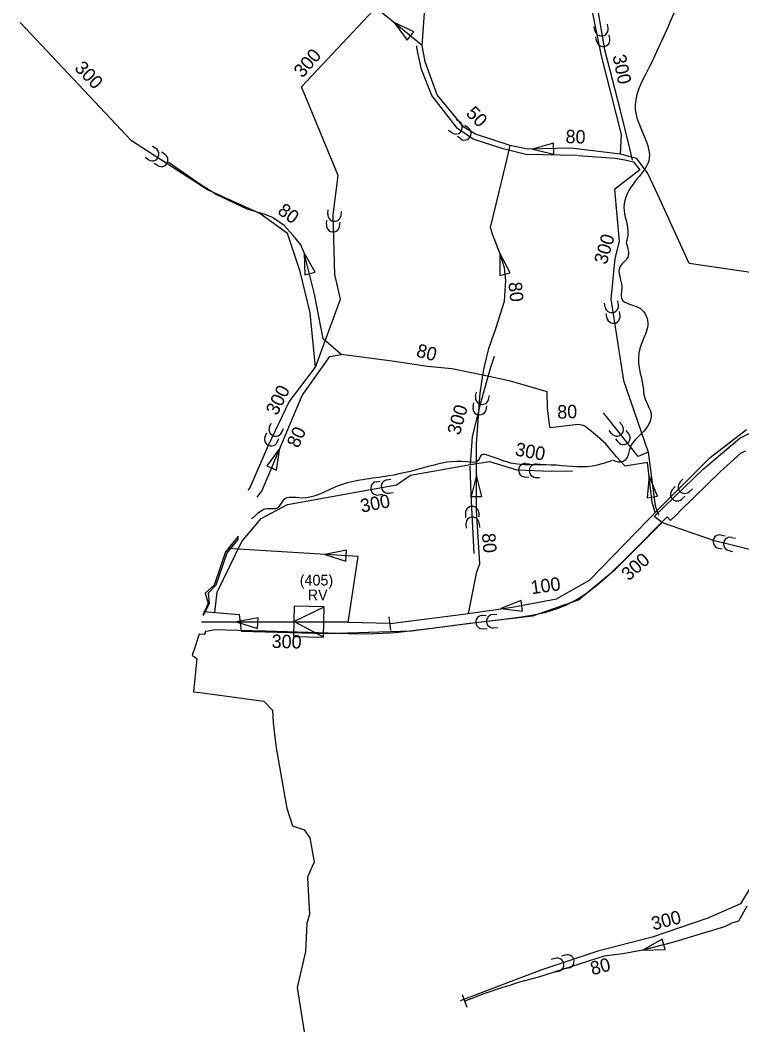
# Model space of a CAD drawing. Extents: x -438814 to -433692, y -1130252 to -1121149.
# Drawn here: x -438788 to -438249, y -1124695 to -1123942 of the extents above; entities that cross this region are included whole.
import ezdxf

# ---------------------------------------------------------------- set-up
doc = ezdxf.new("R2010")
doc.units = 0
for name, color, linetype in [('Vrstva 10', 7, 'Continuous'), ('Vrstva 11', 7, 'Continuous'), ('Vrstva 12', 7, 'Continuous'), ('Vrstva 13', 7, 'Continuous'), ('Vrstva 14', 7, 'Continuous'), ('Vrstva 19', 7, 'Continuous'), ('Vrstva 34', 7, 'Continuous'), ('Vrstva 36', 7, 'Continuous'), ('Vrstva 38', 7, 'Continuous'), ('Vrstva 39', 7, 'Continuous'), ('Vrstva 46', 7, 'Continuous'), ('Vrstva 48', 7, 'Continuous'), ('Vrstva 49', 7, 'Continuous'), ('WT - vodni a vodnich toku', 7, 'Continuous')]:
    doc.layers.add(name, color=color, linetype=linetype)

# ---------------------------------------------------------------- blocks, each defined once
blk = doc.blocks.new('REDUK2')
at = {"layer": 'Vrstva 11'}
for p, q in [((11.906, 10.975), (-10.548, 10.975)), ((-10.548, 10.975), (-10.548, -11.657)), ((-10.548, 10.975), (11.906, -0.341)), ((11.906, -11.657), (11.906, 10.975)), ((11.906, -0.341), (-10.548, -11.657)), ((-10.548, -11.657), (11.906, -11.657))]:
    blk.add_line(p, q, dxfattribs=at)

msp = doc.modelspace()

# ---------------------------------------------------------------- linework, layer by layer
at = {"layer": 'Vrstva 11'}
for points in [[(-438442.88, -1124207.02), (-438441.6, -1124200.42), (-438438.29, -1124186.93), (-438433.03, -1124171.38), (-438426.62, -1124151.63), (-438425.76, -1124136.25), (-438426.82, -1124126.85), (-438430.11, -1124115.96), (-438435.77, -1124101.69), (-438437.1, -1124096.6), (-438432.95, -1124079.29), (-438425.3, -1124047.44), (-438422.48, -1124035.55)], [(-438314.06, -1124309.51), (-438316.51, -1124302.05), (-438319.82, -1124272.26), (-438336.48, -1124274.95), (-438342.98, -1124267.91), (-438351.11, -1124258.21), (-438359.34, -1124250.97), (-438366.81, -1124245.05), (-438368.77, -1124244.22), (-438371.81, -1124243.9), (-438392.24, -1124246.22), (-438392.92, -1124245.73), (-438394.67, -1124231.5), (-438394.89, -1124219.29), (-438422.3, -1124211.37), (-438442.88, -1124207.02), (-438466, -1124202.27), (-438484.14, -1124200.36), (-438510.72, -1124196.48), (-438548.74, -1124191.47), (-438562.22, -1124179.81), (-438568.66, -1124146.38), (-438576.25, -1124115.64), (-438578.87, -1124109.52), (-438584.21, -1124102.8), (-438591.16, -1124095.15), (-438599.97, -1124089.17), (-438605.49, -1124087.04), (-438618.88, -1124082.96), (-438641.95, -1124072.08), (-438654.16, -1124064.24), (-438677.87, -1124047.92)], [(-438512.15, -1124392.34), (-438453.67, -1124384.87), (-438420.93, -1124380.11), (-438387.77, -1124374.02), (-438363.32, -1124359.98), (-438310.95, -1124306.32), (-438304.05, -1124299.37), (-438273.08, -1124268.41), (-438245.92, -1124247.58)], [(-438245.72, -1124603.41), (-438251.96, -1124614.54), (-438256.93, -1124616.08), (-438262.32, -1124618.96), (-438301.2, -1124630.58), (-438323.29, -1124636.23), (-438338.38, -1124638.97), (-438352.36, -1124640.67), (-438401.26, -1124656.44), (-438416.53, -1124660.43), (-438423.56, -1124663.01), (-438428.3, -1124664.11), (-438442.18, -1124668.96), (-438456.25, -1124674.44)]]:
    msp.add_lwpolyline(points, dxfattribs=at)
at = {"layer": 'Vrstva 12'}
for p, q in [((-438511.49, -1124397.3), (-438512.81, -1124387.39)), ((-438454.54, -1124679.13), (-438457.96, -1124669.74))]:
    msp.add_line(p, q, dxfattribs=at)
for points in [[(-438575.84, -1124132.13), (-438568.13, -1124130), (-438576.25, -1124115.64)], [(-438430.27, -1124132.45), (-438422.49, -1124130.59), (-438430.11, -1124115.96)], [(-438320.26, -1124298.58), (-438312.34, -1124297.4), (-438318.65, -1124282.16)], [(-438413.15, -1124383.11), (-438414.21, -1124375.18), (-438429.54, -1124381.27)], [(-438306.8, -1124635.89), (-438308.9, -1124628.18), (-438323.29, -1124636.23)]]:
    msp.add_lwpolyline(points, close=True, dxfattribs=at)
at = {"layer": 'Vrstva 13'}
for p, q in [((-438488.31, -1123960.72), (-438538.54, -1123919.74)), ((-438543.49, -1124391.29), (-438653.03, -1124391.29))]:
    msp.add_line(p, q, dxfattribs=at)
for points in [[(-438339.96, -1124041.86), (-438339.19, -1124027.17), (-438354.13, -1123968.53), (-438362.05, -1123930.71), (-438383.31, -1123905.62), (-438391.01, -1123883.43), (-438409.98, -1123853.88), (-438454.8, -1123791.15), (-438466.52, -1123791.91)], [(-438087.24, -1124107.32), (-438135.67, -1124122.18), (-438154.23, -1124128.52), (-438172.8, -1124139.61), (-438230.97, -1124132.14), (-438288.66, -1124123.51), (-438311.91, -1124072.81), (-438319.59, -1124056.35), (-438327.96, -1124045.25), (-438339.96, -1124041.86), (-438377.03, -1124037.56), (-438409.62, -1124038.24), (-438422.48, -1124035.55), (-438448.29, -1124026.95), (-438457.11, -1124021.74), (-438470.02, -1124006.12), (-438477.01, -1123997.55), (-438486.06, -1123973.09), (-438488.31, -1123960.72), (-438482.88, -1123887.58), (-438483.1, -1123883.34)], [(-438611.36, -1124298.04), (-438607.93, -1124293.61), (-438577.83, -1124222.09), (-438557.1, -1124192.91), (-438548.74, -1124191.47)], [(-438453.67, -1124384.87), (-438447.34, -1124353.84), (-438445.07, -1124347.73), (-438447.56, -1124307.87), (-438447.56, -1124262.81), (-438447.56, -1124258.11), (-438444.9, -1124220.51), (-438442.88, -1124207.02)], [(-438512.15, -1124392.34), (-438543.49, -1124391.63), (-438536.02, -1124342.27), (-438633.41, -1124336.42)]]:
    msp.add_lwpolyline(points, dxfattribs=at)
at = {"layer": 'Vrstva 14'}
for points in [[(-438499.36, -1123956.87), (-438494.3, -1123950.67), (-438509.23, -1123943.65)], [(-438389.82, -1124041.83), (-438389.99, -1124033.83), (-438405.9, -1124038.16)], [(-438604.31, -1124274.69), (-438596.94, -1124277.79), (-438594.42, -1124261.49)], [(-438451.56, -1124297.66), (-438443.56, -1124297.66), (-438447.56, -1124281.66)], [(-438545.12, -1124345.73), (-438544.64, -1124337.74), (-438560.85, -1124340.78)], [(-438611.2, -1124396.16), (-438610.72, -1124388.18), (-438626.93, -1124391.21)]]:
    msp.add_lwpolyline(points, close=True, dxfattribs=at)
at = {"layer": 'Vrstva 19'}
msp.add_line((-438640.64, -1124071.78), (-438640.64, -1124071.78), dxfattribs=at)
at = {"layer": 'Vrstva 34'}
for points in [[(-438618.18, -1124292.86), (-438616.82, -1124291.28), (-438603.03, -1124259.33), (-438587.5, -1124226.84), (-438567.82, -1124200.86), (-438571.9, -1124160.37), (-438579.29, -1124129.63), (-438588.73, -1124101.17), (-438609.56, -1124086.22), (-438648.41, -1124068.62), (-438705.23, -1124031.94), (-438788.44, -1123943.51)], [(-438308.92, -1124317.08), (-438270.78, -1124330.05), (-438232.63, -1124339.64), (-438193.93, -1124319.41), (-438110.46, -1124306.7), (-438076.83, -1124294.13), (-438044.07, -1124289.63), (-437999.41, -1124284.16), (-437947.43, -1124273.24), (-437905, -1124250.33), (-437868.85, -1124217.12), (-437841.76, -1124189.51), (-437857.04, -1124146.16), (-437823.32, -1124112.77), (-437798.27, -1124098.47), (-437778.05, -1124070.78), (-437758.37, -1124050.48), (-437737.69, -1124057.16), (-437694.33, -1124068.4)], [(-438651.16, -1124383.4), (-438624.86, -1124385.67), (-438623.42, -1124398.12), (-438559.85, -1124399.77), (-438496.06, -1124397.82), (-438448.11, -1124391.65), (-438405.45, -1124386.56), (-438371.48, -1124374.64), (-438343.9, -1124351.74), (-438308.92, -1124317.08), (-438314.79, -1124312.41), (-438278.32, -1124277.04), (-438250.99, -1124254.05), (-438206.56, -1124231.61)]]:
    msp.add_lwpolyline(points, dxfattribs=at)
at = {"layer": 'Vrstva 36'}
for points in [[(-438331.07, -1124046.44), (-438333.12, -1124037.74), (-438339.96, -1124009.42), (-438351.73, -1123963.91), (-438357.38, -1123930.49), (-438380.02, -1123902.18), (-438387.48, -1123880.05), (-438405.81, -1123851.29), (-438437.69, -1123807.22), (-438456.25, -1123781.63), (-438506.44, -1123713.82), (-438523.22, -1123647.28), (-438584.56, -1123598.88)], [(-438567.82, -1124200.86), (-438549.24, -1124150.11), (-438553.35, -1124131.76), (-438554.62, -1124087.16), (-438550.82, -1124057.86), (-438578.33, -1123991.75), (-438524.57, -1123934.38), (-438630.16, -1123854.33)], [(-438372.19, -1124043.02), (-438410.87, -1124042.12), (-438427.57, -1124038.05), (-438450.2, -1124030.81), (-438461.74, -1124022.88), (-438480.96, -1123998.07), (-438488.66, -1123978.6), (-438492.28, -1123962.52), (-438492.16, -1123961.14)], [(-438371.71, -1124043.03), (-438344.03, -1124044.86), (-438336.76, -1124046.12), (-438330.43, -1124047.71), (-438325.53, -1124053.6), (-438344.66, -1124068.31), (-438341.04, -1124107.22), (-438344.21, -1124119.87), (-438347.37, -1124150.24), (-438337.88, -1124210.97), (-438319.33, -1124264.41), (-438314.08, -1124304.57), (-438311.64, -1124311.6)], [(-438452.19, -1124273.53), (-438450.66, -1124252.99), (-438444.09, -1124226.49), (-438436.85, -1124200.91), (-438434.16, -1124192.76)], [(-438319.33, -1124264.41), (-438326.93, -1124267.68), (-438340.97, -1124249.8), (-438352.74, -1124235.13)], [(-438642.93, -1124384.11), (-438641.36, -1124369.01), (-438622.81, -1124331.25), (-438608.55, -1124314.04), (-438588.86, -1124303.62), (-438507.38, -1124288.9), (-438496.96, -1124281.66), (-438452.19, -1124273.53), (-438437.93, -1124271.49), (-438417.56, -1124277.6), (-438391.84, -1124278.75), (-438376, -1124278.38)], [(-438449.37, -1124340.04), (-438451.64, -1124296.11), (-438452.35, -1124274.97)], [(-438072.31, -1124326.82), (-438070.72, -1124338.14), (-438084.53, -1124374.6), (-438114.66, -1124405.79), (-438142.73, -1124423), (-438145.44, -1124435.91), (-438147.89, -1124449.85), (-438144.26, -1124487.89), (-438198.59, -1124497.85), (-438204.18, -1124509.07), (-438223.42, -1124565.68), (-438241.08, -1124586.06), (-438250.36, -1124601.69), (-438274.72, -1124612.47), (-438316.37, -1124626.51), (-438356.89, -1124637.15), (-438399.67, -1124651.19), (-438459.74, -1124674)]]:
    msp.add_lwpolyline(points, dxfattribs=at)
at = {"layer": 'Vrstva 38'}
for p, q in [((-438687.06, -1124037.71), (-438689.58, -1124036.09)), ((-438680.34, -1124042.05), (-438682.86, -1124040.43)), ((-438692.48, -1124046.11), (-438695, -1124044.49)), ((-438685.76, -1124050.45), (-438688.28, -1124048.83)), ((-438602.17, -1124245.43), (-438600.92, -1124242.7)), ((-438593.08, -1124249.58), (-438591.83, -1124246.86)), ((-438605.5, -1124252.7), (-438604.25, -1124249.97)), ((-438596.4, -1124256.86), (-438595.16, -1124254.13)), ((-438295.54, -1124286.7), (-438293.4, -1124284.6)), ((-438301.25, -1124292.3), (-438299.11, -1124290.2)), ((-438288.54, -1124293.84), (-438286.4, -1124291.74)), ((-438294.25, -1124299.44), (-438292.11, -1124297.34)), ((-438264.78, -1124326.3), (-438261.86, -1124326.97)), ((-438256.99, -1124328.09), (-438254.06, -1124328.76)), ((-438267.02, -1124336.04), (-438264.1, -1124336.72)), ((-438259.23, -1124337.83), (-438256.3, -1124338.51)), ((-438443.49, -1124386.3), (-438440.5, -1124386.07)), ((-438435.51, -1124385.7), (-438432.52, -1124385.48)), ((-438442.75, -1124396.27), (-438439.76, -1124396.05)), ((-438434.77, -1124395.68), (-438431.78, -1124395.46))]:
    msp.add_line(p, q, dxfattribs=at)
for centre, start, end in [((-438689.77, -1124041.91), 237.15049, 57.15156), ((-438683.05, -1124046.25), 237.15049, 57.15156), ((-438597.62, -1124247.5), 155.42113, 335.4222), ((-438600.95, -1124254.78), 155.42113, 335.4222), ((-438297.75, -1124295.87), 134.45249, 314.45356), ((-438292.04, -1124290.27), 134.45249, 314.45356), ((-438265.9, -1124331.17), 77.05789, 257.05896), ((-438258.11, -1124332.96), 77.05789, 257.05896), ((-438443.12, -1124391.28), 94.24012, 274.24119), ((-438435.14, -1124390.69), 94.24012, 274.24119)]:
    msp.add_arc(centre, 5, start, end, dxfattribs=at)
at = {"layer": 'Vrstva 39'}
for p, q in [((-438349.38, -1123947.84), (-438349.88, -1123944.88)), ((-438359.24, -1123949.51), (-438359.74, -1123946.55)), ((-438348.04, -1123955.73), (-438348.54, -1123952.77)), ((-438357.9, -1123957.4), (-438358.41, -1123954.44)), ((-438460.35, -1124017.77), (-438462.83, -1124016.07)), ((-438453.76, -1124022.3), (-438456.23, -1124020.6)), ((-438466.01, -1124026.02), (-438468.49, -1124024.32)), ((-438459.42, -1124030.54), (-438461.89, -1124028.85)), ((-438558.71, -1124086.37), (-438558.33, -1124083.39)), ((-438548.8, -1124087.65), (-438548.41, -1124084.68)), ((-438559.74, -1124094.3), (-438559.35, -1124091.33)), ((-438549.82, -1124095.58), (-438549.44, -1124092.61)), ((-438351.52, -1124156.06), (-438351.98, -1124153.09)), ((-438341.64, -1124154.52), (-438342.1, -1124151.55)), ((-438350.29, -1124163.96), (-438350.75, -1124161)), ((-438340.41, -1124162.42), (-438340.87, -1124159.46)), ((-438448.29, -1124222.65), (-438447.57, -1124219.74)), ((-438438.59, -1124225.05), (-438437.86, -1124222.14)), ((-438450.22, -1124230.42), (-438449.5, -1124227.5)), ((-438440.51, -1124232.82), (-438439.79, -1124229.91)), ((-438338.88, -1124244.37), (-438340.73, -1124242.01)), ((-438346.74, -1124250.55), (-438348.59, -1124248.19)), ((-438341.8, -1124256.84), (-438343.65, -1124254.48)), ((-438333.93, -1124250.66), (-438335.79, -1124248.3)), ((-438411, -1124272.89), (-438408, -1124273.03)), ((-438403.01, -1124273.25), (-438400.01, -1124273.38)), ((-438514.63, -1124285.13), (-438511.68, -1124284.6)), ((-438411.44, -1124282.88), (-438408.44, -1124283.02)), ((-438403.45, -1124283.24), (-438400.45, -1124283.37)), ((-438522.5, -1124286.55), (-438519.55, -1124286.02)), ((-438520.72, -1124296.39), (-438517.77, -1124295.86)), ((-438512.85, -1124294.97), (-438509.9, -1124294.44)), ((-438455.92, -1124310.14), (-438455.77, -1124313.14)), ((-438445.93, -1124309.63), (-438445.78, -1124312.63)), ((-438455.51, -1124318.13), (-438455.35, -1124321.13)), ((-438445.52, -1124317.62), (-438445.37, -1124320.61)), ((-438388.89, -1124642.39), (-438391.73, -1124643.32)), ((-438381.28, -1124639.9), (-438384.13, -1124640.83)), ((-438385.77, -1124651.89), (-438388.62, -1124652.83)), ((-438378.17, -1124649.4), (-438381.02, -1124650.33))]:
    msp.add_line(p, q, dxfattribs=at)
for centre, start, end in [((-438354.31, -1123948.67), 189.5971, 9.59817), ((-438352.97, -1123956.56), 189.5971, 9.59817), ((-438463.18, -1124021.89), 235.53025, 55.53133), ((-438456.59, -1124026.42), 235.53025, 55.53133), ((-438553.75, -1124087.01), 172.62343, 352.6245), ((-438554.78, -1124094.94), 172.62343, 352.6245), ((-438346.58, -1124155.29), 188.87741, 8.87848), ((-438345.35, -1124163.19), 188.87741, 8.87848), ((-438443.44, -1124223.85), 166.08442, 346.08549), ((-438445.36, -1124231.62), 166.08442, 346.08549), ((-438342.81, -1124247.46), 218.14774, 38.14881), ((-438337.87, -1124253.75), 218.14774, 38.14881), ((-438411.22, -1124277.89), 87.4505, 267.45157), ((-438403.23, -1124278.24), 87.4505, 267.45157), ((-438521.61, -1124291.47), 100.2385, 280.23957), ((-438513.74, -1124290.05), 100.2385, 280.23957), ((-438450.93, -1124309.89), 2.94878, 182.94985), ((-438450.52, -1124317.88), 2.94878, 182.94985), ((-438387.33, -1124647.14), 288.16815, 108.16922), ((-438379.72, -1124644.65), 288.16815, 108.16922)]:
    msp.add_arc(centre, 5, start, end, dxfattribs=at)
at = {"layer": 'Vrstva 46'}
for p, q in [((-438655.04, -1124401.08), (-438658.72, -1124412.5)), ((-438658.72, -1124412.5), (-438659.38, -1124414.56)), ((-438659.38, -1124414.56), (-438659.93, -1124416.28)), ((-438659.93, -1124416.28), (-438659.46, -1124416.56)), ((-438659.46, -1124416.56), (-438656.47, -1124418.39)), ((-438656.47, -1124418.39), (-438658.78, -1124440.93)), ((-438658.78, -1124440.93), (-438659.03, -1124443.37)), ((-438659.03, -1124443.37), (-438652.37, -1124444.25)), ((-438652.37, -1124444.25), (-438606.34, -1124450.3)), ((-438606.34, -1124450.3), (-438599.86, -1124457.06)), ((-438599.86, -1124457.06), (-438599.4, -1124466.49)), ((-438599.4, -1124466.49), (-438599.05, -1124470.49)), ((-438599.05, -1124470.49), (-438598.23, -1124477.26)), ((-438598.23, -1124477.26), (-438597.27, -1124485.26)), ((-438597.27, -1124485.26), (-438589.92, -1124526.35)), ((-438589.92, -1124526.35), (-438589.22, -1124530.3)), ((-438589.22, -1124530.3), (-438584.94, -1124543.38)), ((-438584.94, -1124543.38), (-438576.34, -1124546.48)), ((-438576.34, -1124546.48), (-438572.02, -1124552.38)), ((-438572.02, -1124552.38), (-438568.82, -1124570.46)), ((-438568.82, -1124570.46), (-438570.23, -1124573.74)), ((-438570.23, -1124573.74), (-438573.74, -1124581.88)), ((-438573.74, -1124581.88), (-438573.26, -1124592.07)), ((-438573.26, -1124592.07), (-438572.45, -1124609.51)), ((-438574.27, -1124616.44), (-438575.4, -1124637.35)), ((-438572.45, -1124609.51), (-438574.27, -1124616.44)), ((-438575.4, -1124637.35), (-438581.51, -1124664.14)), ((-438581.51, -1124664.14), (-438576.35, -1124697.33))]:
    msp.add_line(p, q, dxfattribs=at)
msp.add_lwpolyline([(-438246.74, -1124263.66), (-438250.08, -1124265.17), (-438265.35, -1124278.76), (-438295.42, -1124308.34), (-438297.79, -1124310.68), (-438302.59, -1124315.4), (-438305.26, -1124312.72), (-438332.57, -1124340.4), (-438348.6, -1124355.96), (-438358.01, -1124364.22), (-438361.95, -1124367.33), (-438362.42, -1124367.71), (-438364.9, -1124369.67), (-438371.11, -1124373.64), (-438380.55, -1124378.65), (-438387.31, -1124381.45), (-438396.81, -1124384.29), (-438405.16, -1124386.13), (-438414.27, -1124387.73), (-438427.1, -1124389.35), (-438452.5, -1124392.47), (-438477.24, -1124395.72), (-438487.22, -1124396.92), (-438505.93, -1124399.07), (-438511.88, -1124399.58), (-438524.23, -1124400.15), (-438530.77, -1124400.22), (-438543.15, -1124400.06), (-438573.31, -1124399.08), (-438604.61, -1124398.17), (-438625.79, -1124397.57), (-438643.04, -1124397.1), (-438648.13, -1124398.21), (-438650.19, -1124398.35), (-438650.2, -1124399.93), (-438650.7, -1124399.94), (-438650.69, -1124400.54), (-438654.8, -1124400.32), (-438655.04, -1124401.08)], dxfattribs=at)
at = {"layer": 'WT - vodni a vodnich toku'}
for points in [[(-438651.37, -1124385.99), (-438646.94, -1124377.5), (-438647.8, -1124369.55), (-438642.1, -1124363.51), (-438633.82, -1124339.51), (-438625.7, -1124329.67), (-438625.7, -1124327.21)], [(-438625.7, -1124327.21), (-438632.61, -1124335.87), (-438635.01, -1124338.88), (-438639.06, -1124350.64)], [(-438639.06, -1124350.64), (-438643.59, -1124363.78), (-438650.28, -1124369.64), (-438648.05, -1124377.24), (-438649.34, -1124380.12), (-438651.29, -1124384.47), (-438651.97, -1124386.01)], [(-438651.97, -1124386.01), (-438651.37, -1124385.99)]]:
    msp.add_lwpolyline(points, dxfattribs=at)
for points in [[(-438272.48, -1123825.81), (-438280.98, -1123839.11), (-438286.48, -1123854.14), (-438284.48, -1123881.18), (-438286.98, -1123903.22), (-438299.5, -1123935.28), (-438319.53, -1123978.85), (-438329.04, -1124008.91), (-438319, -1124047), (-438329.01, -1124062.04), (-438337.52, -1124081.58), (-438334.52, -1124101.12), (-438335.81, -1124108.24)], [(-438335.81, -1124108.24), (-438334.65, -1124118.84), (-438340.64, -1124126.33), (-438339.14, -1124140.79), (-438339.14, -1124150.27), (-438325.17, -1124157.26), (-438319.69, -1124169.73), (-438324.17, -1124182.71), (-438326.67, -1124194.68), (-438323.18, -1124216.13), (-438322.18, -1124223.12), (-438317.19, -1124236.59), (-438321.18, -1124247.07), (-438332.65, -1124260.54), (-438335.15, -1124268.52), (-438338.14, -1124271.52), (-438345.17, -1124270.75)], [(-438346.36, -1124270.75), (-438361.29, -1124274.93), (-438391.75, -1124274.03), (-438422.22, -1124272.54), (-438438.94, -1124266.86), (-438444.02, -1124266.56), (-438446.28, -1124270.72), (-438454.26, -1124271.71), (-438483.69, -1124275.21), (-438513.12, -1124282.2), (-438551.02, -1124289.69), (-438578.46, -1124298.67), (-438591.92, -1124300.17), (-438596.41, -1124306.16), (-438603.89, -1124306.66), (-438613.17, -1124312.15), (-438615.62, -1124314.33)]]:
    msp.add_spline(points, degree=3, dxfattribs=at)

# ---------------------------------------------------------------- block references
at = {"layer": 'Vrstva 10', "rotation": 178.85302660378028}
msp.add_blockref('REDUK2', (-438572.19, -1124391.39), dxfattribs=at)

# ---------------------------------------------------------------- texts
at = {"layer": 'Vrstva 19'}
for s, rotation, p in [('50', 314.97409, (-438456.1, -1124012.11)), ('80', 358.80526, (-438381.16, -1124033.74)), ('80', 323.94902, (-438596.92, -1124085.8)), ('80', 275.81417, (-438423.81, -1124137.83)), ('80', 345.24603, (-438493.21, -1124192.87)), ('80', 1.79005, (-438387.14, -1124239.45)), ('80', 65.77511, (-438580.66, -1124261.96)), ('80', 274.85098, (-438443.62, -1124325.25)), ('100', 8.12569, (-438406.41, -1124370.57)), ('80', 14.53923, (-438361.13, -1124655.09))]:
    msp.add_text(s, height=10, rotation=rotation, dxfattribs=at).set_placement(p)
for s, p in [('(405)', (-438579.62, -1124364.03)), ('  RV', (-438579.62, -1124375.03))]:
    msp.add_text(s, height=8, dxfattribs=at).set_placement(p)
at = {"layer": 'Vrstva 48'}
for rotation, p in [(314.27406, (-438748.42, -1123978.22)), (63.45539, (-438596.59, -1124237.65)), (41.73607, (-438333.96, -1124361.06)), (358.50378, (-438600.71, -1124410.54))]:
    msp.add_text('300', height=10, rotation=rotation, dxfattribs=at).set_placement(p)
at = {"layer": 'Vrstva 49'}
for rotation, p in [(49.09136, (-438577.51, -1123985.52)), (281.84042, (-438346.08, -1123968.57)), (73.69028, (-438350.49, -1124124.79)), (73.69028, (-438460.18, -1124252.24)), (349.75805, (-438419.25, -1124266.83)), (10.80488, (-438533.39, -1124309.62)), (14.53923, (-438315.55, -1124621.57))]:
    msp.add_text('300', height=10, rotation=rotation, dxfattribs=at).set_placement(p)

doc.saveas('drawing.dxf')
